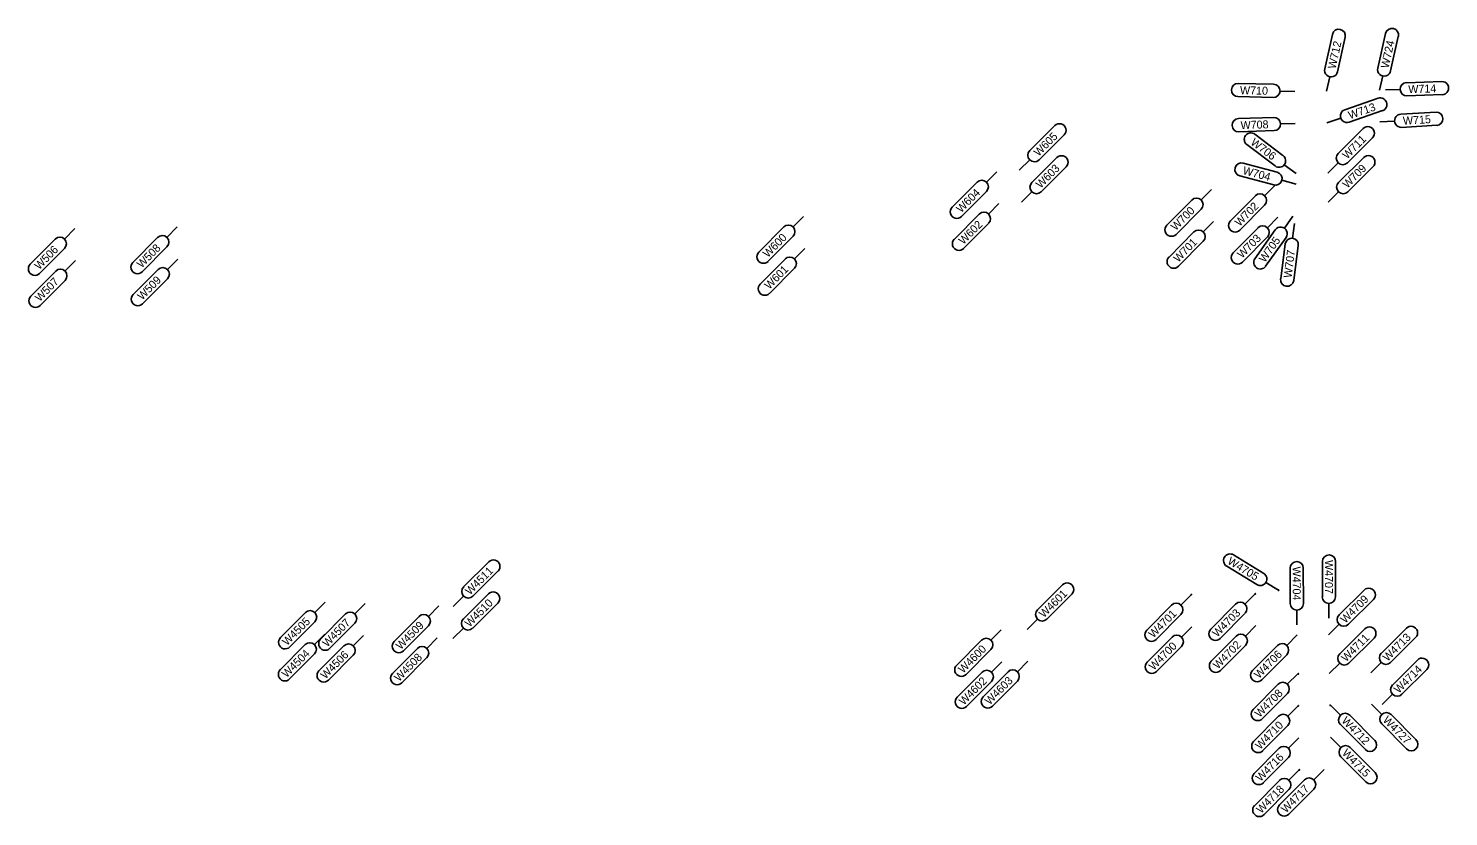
# Model space of a CAD drawing. Extents: x 12479652 to 12487250, y 9842710 to 9846560.
# Drawn here: x 12480701.1 to 12480922.9, y 9842714.9 to 9842838 of the extents above; entities that cross this region are included whole.
import ezdxf

# ---------------------------------------------------------------- set-up
doc = ezdxf.new("R2010")
doc.units = 0
doc.layers.add('_CIVIL_CONSTRUCTION', color=7, linetype='Continuous')
doc.layers.add('TextAlignmentLrg', color=7, linetype='Continuous')

msp = doc.modelspace()

# ---------------------------------------------------------------- linework, layer by layer
at = {"layer": '_CIVIL_CONSTRUCTION'}
for p, q in [((12480904.76, 9842837.05), (12480903.57, 9842831.66)), ((12480905.57, 9842831.22), (12480906.76, 9842836.6)), ((12480913.05, 9842837.18), (12480911.86, 9842831.8)), ((12480913.86, 9842831.35), (12480915.06, 9842836.74)), ((12480903.85, 9842828.19), (12480904.34, 9842830.44)), ((12480912.14, 9842828.33), (12480912.64, 9842830.57)), ((12480921.86, 9842829.69), (12480916.34, 9842829.51)), ((12480895.53, 9842827.21), (12480890.01, 9842827.34)), ((12480890.06, 9842829.39), (12480895.57, 9842829.26)), ((12480898.88, 9842828.15), (12480896.58, 9842828.21)), ((12480913.05, 9842828.38), (12480915.35, 9842828.45)), ((12480916.41, 9842827.46), (12480921.92, 9842827.64)), ((12480911.92, 9842827.08), (12480906.7, 9842825.28)), ((12480907.37, 9842823.34), (12480912.59, 9842825.14)), ((12480861.4, 9842822.8), (12480857.48, 9842818.91)), ((12480890.08, 9842823.89), (12480895.6, 9842824.07)), ((12480898.96, 9842823.16), (12480896.66, 9842823.08)), ((12480903.89, 9842823.22), (12480906.07, 9842823.97)), ((12480912.18, 9842823.37), (12480914.48, 9842823.5)), ((12480920.95, 9842824.9), (12480915.45, 9842824.58)), ((12480915.56, 9842822.53), (12480921.07, 9842822.85)), ((12480858.93, 9842817.45), (12480862.84, 9842821.34)), ((12480895.67, 9842822.02), (12480890.15, 9842821.84)), ((12480892.64, 9842821.47), (12480897.04, 9842818.14)), ((12480909.58, 9842822.35), (12480905.67, 9842818.46)), ((12480907.11, 9842817), (12480911.03, 9842820.89)), ((12480895.81, 9842816.5), (12480891.41, 9842819.83)), ((12480855.85, 9842815.84), (12480857.48, 9842817.46)), ((12480861.73, 9842817.81), (12480857.81, 9842813.92)), ((12480859.26, 9842812.46), (12480863.17, 9842816.35)), ((12480890.83, 9842816.94), (12480896.16, 9842815.52)), ((12480899.08, 9842815.31), (12480897.24, 9842816.7)), ((12480904.03, 9842815.38), (12480905.66, 9842817.01)), ((12480909.65, 9842817.82), (12480905.74, 9842813.93)), ((12480907.19, 9842812.47), (12480911.1, 9842816.36)), ((12480845.38, 9842810.06), (12480849.27, 9842813.98)), ((12480852.34, 9842815.61), (12480850.72, 9842813.98)), ((12480895.63, 9842813.54), (12480890.3, 9842814.96)), ((12480899.11, 9842813.68), (12480896.88, 9842814.27)), ((12480850.72, 9842812.53), (12480846.83, 9842808.62)), ((12480856.18, 9842810.85), (12480857.81, 9842812.47)), ((12480885.86, 9842812.82), (12480884.24, 9842811.19)), ((12480888.84, 9842807.93), (12480892.73, 9842811.84)), ((12480895.8, 9842813.48), (12480894.18, 9842811.84)), ((12480904.1, 9842810.85), (12480905.73, 9842812.48)), ((12480852.67, 9842810.62), (12480851.05, 9842808.99)), ((12480878.9, 9842807.27), (12480882.79, 9842811.18)), ((12480884.24, 9842809.74), (12480880.35, 9842805.82)), ((12480894.18, 9842810.39), (12480890.29, 9842806.48)), ((12480822.13, 9842808.6), (12480820.51, 9842806.97)), ((12480845.71, 9842805.08), (12480849.6, 9842808.99)), ((12480851.05, 9842807.54), (12480847.16, 9842803.63)), ((12480886.2, 9842807.83), (12480884.58, 9842806.2)), ((12480896.22, 9842808.49), (12480894.6, 9842806.86)), ((12480898.6, 9842808.65), (12480897.27, 9842806.77)), ((12480898.84, 9842807.5), (12480898.55, 9842805.21)), ((12480701.35, 9842801.17), (12480705.24, 9842805.08)), ((12480708.31, 9842806.72), (12480706.69, 9842805.08)), ((12480717.35, 9842801.42), (12480721.24, 9842805.34)), ((12480724.31, 9842806.97), (12480722.69, 9842805.34)), ((12480815.17, 9842803.06), (12480819.06, 9842806.97)), ((12480820.51, 9842805.52), (12480816.62, 9842801.61)), ((12480879.24, 9842802.28), (12480883.13, 9842806.2)), ((12480889.26, 9842802.94), (12480893.15, 9842806.86)), ((12480894.6, 9842805.41), (12480890.71, 9842801.5)), ((12480892.66, 9842802.02), (12480895.84, 9842806.53)), ((12480897.52, 9842805.34), (12480894.33, 9842800.84)), ((12480706.7, 9842803.63), (12480702.81, 9842799.72)), ((12480722.69, 9842803.89), (12480718.8, 9842799.98)), ((12480822.33, 9842803.61), (12480820.71, 9842801.98)), ((12480884.59, 9842804.75), (12480880.7, 9842800.84)), ((12480896.69, 9842798.86), (12480897.4, 9842804.33)), ((12480899.43, 9842804.06), (12480898.72, 9842798.59)), ((12480708.39, 9842801.72), (12480706.77, 9842800.09)), ((12480724.39, 9842801.97), (12480722.77, 9842800.34)), ((12480815.37, 9842798.06), (12480819.26, 9842801.97)), ((12480701.43, 9842796.17), (12480705.32, 9842800.08)), ((12480706.78, 9842798.63), (12480702.89, 9842794.72)), ((12480717.43, 9842796.43), (12480721.32, 9842800.34)), ((12480722.77, 9842798.89), (12480718.89, 9842794.98)), ((12480820.72, 9842800.52), (12480816.83, 9842796.61)), ((12480772.97, 9842754.67), (12480769.05, 9842750.78)), ((12480892.96, 9842751.13), (12480888.26, 9842754)), ((12480889.33, 9842755.75), (12480894.03, 9842752.88)), ((12480903.2, 9842749.21), (12480903.22, 9842754.73)), ((12480905.27, 9842754.72), (12480905.25, 9842749.2)), ((12480770.5, 9842749.32), (12480774.41, 9842753.21)), ((12480898.19, 9842748.15), (12480898.16, 9842753.67)), ((12480900.22, 9842753.68), (12480900.24, 9842748.16)), ((12480772.92, 9842749.67), (12480769.01, 9842745.78)), ((12480862.61, 9842751.08), (12480858.7, 9842747.19)), ((12480860.15, 9842745.73), (12480864.06, 9842749.62)), ((12480882.73, 9842749.55), (12480881.11, 9842747.92)), ((12480892.73, 9842749.71), (12480891.1, 9842748.08)), ((12480896.34, 9842750.27), (12480894.37, 9842751.47)), ((12480909.72, 9842750.27), (12480905.81, 9842746.38)), ((12480747.4, 9842748.38), (12480745.78, 9842746.75)), ((12480753.67, 9842748.17), (12480752.05, 9842746.54)), ((12480765.16, 9842747.78), (12480763.54, 9842746.15)), ((12480767.42, 9842747.71), (12480769.05, 9842749.33)), ((12480770.46, 9842744.32), (12480774.37, 9842748.21)), ((12480875.77, 9842744.01), (12480879.65, 9842747.92)), ((12480885.76, 9842744.17), (12480889.65, 9842748.08)), ((12480904.21, 9842745.88), (12480904.22, 9842748.18)), ((12480907.26, 9842744.92), (12480911.17, 9842748.81)), ((12480740.44, 9842742.84), (12480744.33, 9842746.75)), ((12480745.79, 9842745.3), (12480741.9, 9842741.39)), ((12480746.71, 9842742.62), (12480750.59, 9842746.54)), ((12480758.2, 9842742.23), (12480762.09, 9842746.15)), ((12480857.06, 9842744.12), (12480858.7, 9842745.74)), ((12480881.11, 9842746.47), (12480877.22, 9842742.56)), ((12480891.11, 9842746.63), (12480887.22, 9842742.72)), ((12480899.23, 9842744.83), (12480899.22, 9842747.13)), ((12480747.36, 9842743.38), (12480745.74, 9842741.75)), ((12480752.05, 9842745.09), (12480748.16, 9842741.18)), ((12480753.41, 9842743.18), (12480751.79, 9842741.55)), ((12480763.54, 9842744.7), (12480759.65, 9842740.79)), ((12480767.37, 9842742.7), (12480769, 9842744.33)), ((12480853.04, 9842744.08), (12480851.41, 9842742.44)), ((12480875.85, 9842739.01), (12480879.74, 9842742.92)), ((12480882.81, 9842744.55), (12480881.19, 9842742.92)), ((12480885.84, 9842739.17), (12480889.73, 9842743.08)), ((12480892.81, 9842744.72), (12480891.18, 9842743.08)), ((12480899.25, 9842743.25), (12480897.63, 9842741.62)), ((12480904.17, 9842743.3), (12480905.8, 9842744.93)), ((12480909.82, 9842744.2), (12480905.91, 9842740.31)), ((12480916.32, 9842744.31), (12480912.41, 9842740.42)), ((12480740.4, 9842737.83), (12480744.29, 9842741.75)), ((12480746.45, 9842737.63), (12480750.34, 9842741.54)), ((12480757.94, 9842737.24), (12480761.83, 9842741.15)), ((12480764.91, 9842742.79), (12480763.28, 9842741.16)), ((12480846.07, 9842738.53), (12480849.96, 9842742.44)), ((12480851.42, 9842740.99), (12480847.53, 9842737.08)), ((12480881.19, 9842741.47), (12480877.3, 9842737.56)), ((12480891.19, 9842741.63), (12480887.3, 9842737.72)), ((12480892.29, 9842737.7), (12480896.18, 9842741.61)), ((12480907.35, 9842738.86), (12480911.27, 9842742.75)), ((12480913.85, 9842738.96), (12480917.77, 9842742.85)), ((12480745.74, 9842740.3), (12480741.85, 9842736.39)), ((12480751.8, 9842740.1), (12480747.91, 9842736.18)), ((12480763.29, 9842739.71), (12480759.4, 9842735.79)), ((12480853.12, 9842739.08), (12480851.49, 9842737.45)), ((12480857.17, 9842739.14), (12480855.55, 9842737.51)), ((12480897.63, 9842740.17), (12480893.74, 9842736.25)), ((12480904.27, 9842737.24), (12480905.9, 9842738.86)), ((12480910.77, 9842737.34), (12480912.4, 9842738.97)), ((12480918.08, 9842739.33), (12480914.17, 9842735.44)), ((12480846.15, 9842733.53), (12480850.04, 9842737.44)), ((12480850.21, 9842733.59), (12480854.1, 9842737.51)), ((12480899.35, 9842737.18), (12480897.72, 9842735.55)), ((12480915.62, 9842733.99), (12480919.53, 9842737.88)), ((12480851.5, 9842735.99), (12480847.61, 9842732.08)), ((12480855.55, 9842736.06), (12480851.66, 9842732.15)), ((12480892.38, 9842731.64), (12480896.27, 9842735.55)), ((12480897.73, 9842734.1), (12480893.84, 9842730.19)), ((12480899.43, 9842732.19), (12480897.81, 9842730.55)), ((12480904.4, 9842732.35), (12480906.02, 9842730.72)), ((12480910.85, 9842732.46), (12480912.48, 9842730.83)), ((12480912.53, 9842732.37), (12480914.16, 9842733.99)), ((12480892.46, 9842726.64), (12480896.35, 9842730.55)), ((12480911.36, 9842726.8), (12480907.47, 9842730.72)), ((12480917.82, 9842726.91), (12480913.93, 9842730.82)), ((12480897.81, 9842729.1), (12480893.92, 9842725.19)), ((12480906.02, 9842729.27), (12480909.91, 9842725.36)), ((12480912.47, 9842729.37), (12480916.36, 9842725.46)), ((12480892.54, 9842721.64), (12480896.43, 9842725.55)), ((12480899.51, 9842727.19), (12480897.89, 9842725.55)), ((12480904.48, 9842727.3), (12480906.1, 9842725.67)), ((12480911.44, 9842721.76), (12480907.55, 9842725.67)), ((12480897.89, 9842724.1), (12480894, 9842720.19)), ((12480906.1, 9842724.22), (12480909.99, 9842720.31)), ((12480899.59, 9842722.19), (12480897.97, 9842720.56)), ((12480903.46, 9842722.25), (12480901.84, 9842720.62)), ((12480892.63, 9842716.64), (12480896.51, 9842720.55)), ((12480897.97, 9842719.1), (12480894.08, 9842715.19)), ((12480896.5, 9842716.7), (12480900.39, 9842720.61)), ((12480901.85, 9842719.17), (12480897.96, 9842715.25))]:
    msp.add_line(p, q, dxfattribs=at)
for centre, start, end in [((12480905.76, 9842836.83), 347.4836, 167.4836), ((12480914.06, 9842836.96), 347.4836, 167.4836), ((12480904.57, 9842831.44), 167.4836, 347.4836), ((12480912.86, 9842831.57), 167.4836, 347.4836), ((12480916.38, 9842828.49), 91.8083, 271.8083), ((12480921.89, 9842828.66), 271.8083, 91.8083), ((12480890.03, 9842828.36), 88.6585, 268.6585), ((12480895.55, 9842828.23), 268.6585, 88.6585), ((12480907.04, 9842824.31), 109.0453, 289.0453), ((12480912.25, 9842826.11), 289.0453, 109.0453), ((12480862.12, 9842822.07), 314.8298, 134.8298), ((12480890.12, 9842822.86), 91.9126, 271.9126), ((12480895.63, 9842823.05), 271.9126, 91.9126), ((12480915.51, 9842823.56), 93.2871, 273.2871), ((12480921.01, 9842823.87), 273.2871, 93.2871), ((12480892.03, 9842820.65), 52.8886, 232.8886), ((12480910.3, 9842821.62), 314.8298, 134.8298), ((12480858.21, 9842818.18), 134.8298, 314.8298), ((12480906.39, 9842817.73), 134.8298, 314.8298), ((12480862.45, 9842817.08), 314.8298, 134.8298), ((12480890.56, 9842815.95), 75.0991, 255.0991), ((12480896.43, 9842817.32), 232.8886, 52.8886), ((12480910.38, 9842817.09), 314.8298, 134.8298), ((12480849.99, 9842813.25), 315.1702, 135.1702), ((12480858.54, 9842813.19), 134.8298, 314.8298), ((12480895.89, 9842814.53), 255.0991, 75.0991), ((12480906.46, 9842813.2), 134.8298, 314.8298), ((12480893.45, 9842811.12), 315.1702, 135.1702), ((12480846.1, 9842809.34), 135.1702, 315.1702), ((12480883.52, 9842810.46), 315.1702, 135.1702), ((12480819.78, 9842806.25), 315.1702, 135.1702), ((12480850.32, 9842808.27), 315.1702, 135.1702), ((12480879.63, 9842806.55), 135.1702, 315.1702), ((12480889.56, 9842807.2), 135.1702, 315.1702), ((12480705.97, 9842804.36), 315.1702, 135.1702), ((12480721.97, 9842804.61), 315.1702, 135.1702), ((12480846.43, 9842804.35), 135.1702, 315.1702), ((12480883.86, 9842805.47), 315.1702, 135.1702), ((12480893.87, 9842806.13), 315.1702, 135.1702), ((12480896.68, 9842805.94), 324.7706, 144.7706), ((12480898.42, 9842804.2), 352.5918, 172.5918), ((12480815.89, 9842802.33), 135.1702, 315.1702), ((12480889.98, 9842802.22), 135.1702, 315.1702), ((12480702.08, 9842800.44), 135.1702, 315.1702), ((12480718.08, 9842800.7), 135.1702, 315.1702), ((12480722.05, 9842799.61), 315.1702, 135.1702), ((12480819.99, 9842801.25), 315.1702, 135.1702), ((12480879.97, 9842801.56), 135.1702, 315.1702), ((12480893.5, 9842801.43), 144.7706, 324.7706), ((12480706.05, 9842799.36), 315.1702, 135.1702), ((12480897.7, 9842798.73), 172.5918, 352.5918), ((12480702.16, 9842795.44), 135.1702, 315.1702), ((12480718.16, 9842795.7), 135.1702, 315.1702), ((12480816.1, 9842797.34), 135.1702, 315.1702), ((12480773.69, 9842753.94), 314.8298, 134.8298), ((12480888.79, 9842754.88), 58.5765, 238.5765), ((12480899.19, 9842753.68), 0.26, 180.26), ((12480904.24, 9842754.72), 359.823, 179.823), ((12480893.5, 9842752), 238.5765, 58.5765), ((12480769.78, 9842750.05), 134.8298, 314.8298), ((12480773.65, 9842748.94), 314.8298, 134.8298), ((12480863.34, 9842750.35), 314.8298, 134.8298), ((12480910.45, 9842749.54), 314.8298, 134.8298), ((12480880.38, 9842747.19), 315.1702, 135.1702), ((12480890.38, 9842747.36), 315.1702, 135.1702), ((12480899.21, 9842748.16), 180.26, 0.26), ((12480904.22, 9842749.21), 179.823, 359.823), ((12480745.06, 9842746.03), 315.1702, 135.1702), ((12480751.32, 9842745.81), 315.1702, 135.1702), ((12480762.82, 9842745.42), 315.1702, 135.1702), ((12480769.73, 9842745.05), 134.8298, 314.8298), ((12480859.42, 9842746.46), 134.8298, 314.8298), ((12480906.53, 9842745.65), 134.8298, 314.8298), ((12480876.49, 9842743.28), 135.1702, 315.1702), ((12480880.46, 9842742.2), 315.1702, 135.1702), ((12480886.49, 9842743.44), 135.1702, 315.1702), ((12480890.46, 9842742.36), 315.1702, 135.1702), ((12480910.54, 9842743.47), 314.8298, 134.8298), ((12480917.04, 9842743.58), 314.8298, 134.8298), ((12480741.17, 9842742.11), 135.1702, 315.1702), ((12480745.02, 9842741.02), 315.1702, 135.1702), ((12480747.43, 9842741.9), 135.1702, 315.1702), ((12480751.07, 9842740.82), 315.1702, 135.1702), ((12480758.93, 9842741.51), 135.1702, 315.1702), ((12480762.56, 9842740.43), 315.1702, 135.1702), ((12480850.69, 9842741.72), 315.1702, 135.1702), ((12480896.9, 9842740.89), 315.1702, 135.1702), ((12480846.8, 9842737.8), 135.1702, 315.1702), ((12480876.57, 9842738.28), 135.1702, 315.1702), ((12480886.57, 9842738.44), 135.1702, 315.1702), ((12480906.63, 9842739.58), 134.8298, 314.8298), ((12480913.13, 9842739.69), 134.8298, 314.8298), ((12480918.8, 9842738.61), 314.8298, 134.8298), ((12480741.13, 9842737.11), 135.1702, 315.1702), ((12480747.18, 9842736.91), 135.1702, 315.1702), ((12480758.67, 9842736.52), 135.1702, 315.1702), ((12480850.77, 9842736.72), 315.1702, 135.1702), ((12480854.82, 9842736.78), 315.1702, 135.1702), ((12480893.01, 9842736.98), 135.1702, 315.1702), ((12480897, 9842734.83), 315.1702, 135.1702), ((12480914.89, 9842734.72), 134.8298, 314.8298), ((12480846.88, 9842732.8), 135.1702, 315.1702), ((12480850.93, 9842732.87), 135.1702, 315.1702), ((12480893.11, 9842730.91), 135.1702, 315.1702), ((12480897.08, 9842729.83), 315.1702, 135.1702), ((12480906.75, 9842729.99), 44.8298, 224.8298), ((12480913.2, 9842730.1), 44.8298, 224.8298), ((12480893.19, 9842725.91), 135.1702, 315.1702), ((12480897.16, 9842724.83), 315.1702, 135.1702), ((12480906.83, 9842724.94), 44.8298, 224.8298), ((12480910.64, 9842726.08), 224.8298, 44.8298), ((12480917.09, 9842726.18), 224.8298, 44.8298), ((12480893.27, 9842720.91), 135.1702, 315.1702), ((12480897.24, 9842719.83), 315.1702, 135.1702), ((12480901.12, 9842719.89), 315.1702, 135.1702), ((12480910.72, 9842721.03), 224.8298, 44.8298), ((12480893.35, 9842715.92), 135.1702, 315.1702), ((12480897.23, 9842715.98), 135.1702, 315.1702)]:
    msp.add_arc(centre, 1.03, start, end, dxfattribs=at)
at = {"layer": 'TextAlignmentLrg'}
for centre in [(12480882.73, 9842749.56), (12480892.73, 9842749.67), (12480896.35, 9842750.26), (12480899.45, 9842737.19), (12480899.43, 9842732.19), (12480904.43, 9842732.27), (12480899.59, 9842722.19)]:
    msp.add_circle(centre, 0.05, dxfattribs=at)

# ---------------------------------------------------------------- texts
at = {"layer": '_CIVIL_CONSTRUCTION'}
for s, rotation, p in [('W712', 77.4836, (12480905.25, 9842831.58)), ('W724', 77.4836, (12480913.53, 9842831.68)), ('W710', 358.6585, (12480890.32, 9842827.72)), ('W714', 1.8083, (12480916.64, 9842827.86)), ('W713', 19.0453, (12480907.5, 9842823.79)), ('W708', 1.9126, (12480890.44, 9842822.24)), ('W715', 3.2871, (12480915.82, 9842822.94)), ('W605', 44.8298, (12480858.85, 9842817.92)), ('W706', 322.8886, (12480891.88, 9842819.96)), ('W711', 44.8298, (12480907.05, 9842817.49)), ('W603', 44.8298, (12480859.17, 9842812.93)), ('W704', 345.0991, (12480890.68, 9842815.26)), ('W709', 44.8298, (12480907.09, 9842812.93)), ('W604', 45.1702, (12480846.76, 9842809.1)), ('W700', 45.1702, (12480880.29, 9842806.31)), ('W702', 45.1702, (12480890.25, 9842806.99)), ('W602', 45.1702, (12480847.12, 9842804.14)), ('W600', 45.1702, (12480816.56, 9842802.1)), ('W701', 45.1702, (12480880.67, 9842801.36)), ('W703', 45.1702, (12480890.65, 9842801.99)), ('W705', 54.7706, (12480894.2, 9842801.32)), ('W506', 45.1702, (12480702.74, 9842800.21)), ('W508', 45.1702, (12480718.74, 9842800.47)), ('W707', 82.5918, (12480898.38, 9842798.96)), ('W601', 45.1702, (12480816.8, 9842797.14)), ('W507', 45.1702, (12480702.83, 9842795.22)), ('W509', 45.1702, (12480718.82, 9842795.47)), ('W4705', 328.5765, (12480888.26, 9842754.46)), ('W4707', 269.823, (12480903.61, 9842754.96)), ('W4511', 44.8298, (12480770.03, 9842749.41)), ('W4704', 270.26, (12480898.55, 9842753.94)), ('W4601', 44.8298, (12480859.69, 9842745.84)), ('W4510', 44.8298, (12480769.97, 9842744.39)), ('W4709', 44.8298, (12480906.77, 9842744.99)), ('W4505', 45.1702, (12480741.45, 9842741.5)), ('W4507', 45.1702, (12480747.72, 9842741.28)), ('W4509', 45.1702, (12480759.2, 9842740.88)), ('W4701', 45.1702, (12480876.8, 9842742.69)), ('W4703', 45.1702, (12480886.77, 9842742.82)), ('W4711', 44.8298, (12480906.9, 9842738.96)), ('W4713', 44.8298, (12480913.38, 9842739.04)), ('W4504', 45.1702, (12480741.39, 9842736.48)), ('W4506', 45.1702, (12480747.45, 9842736.28)), ('W4600', 45.1702, (12480847.07, 9842737.18)), ('W4700', 45.1702, (12480876.84, 9842737.65)), ('W4702', 45.1702, (12480886.86, 9842737.84)), ('W4706', 45.1702, (12480893.28, 9842736.35)), ('W4508', 45.1702, (12480758.94, 9842735.89)), ('W4714', 44.8298, (12480915.12, 9842734.05)), ('W4602', 45.1702, (12480847.17, 9842732.2)), ('W4603', 45.1702, (12480851.21, 9842732.25)), ('W4708', 45.1702, (12480893.38, 9842730.29)), ('W4710', 45.1702, (12480893.46, 9842725.29)), ('W4712', 314.8298, (12480906.1, 9842729.74)), ('W4727', 314.8298, (12480912.55, 9842729.85)), ('W4715', 314.8298, (12480906.18, 9842724.7)), ('W4716', 45.1702, (12480893.54, 9842720.28)), ('W4718', 45.1702, (12480893.62, 9842715.29)), ('W4717', 45.1702, (12480897.51, 9842715.36))]:
    msp.add_text(s, height=1.25, rotation=rotation, dxfattribs=at).set_placement(p)

doc.saveas('drawing.dxf')
